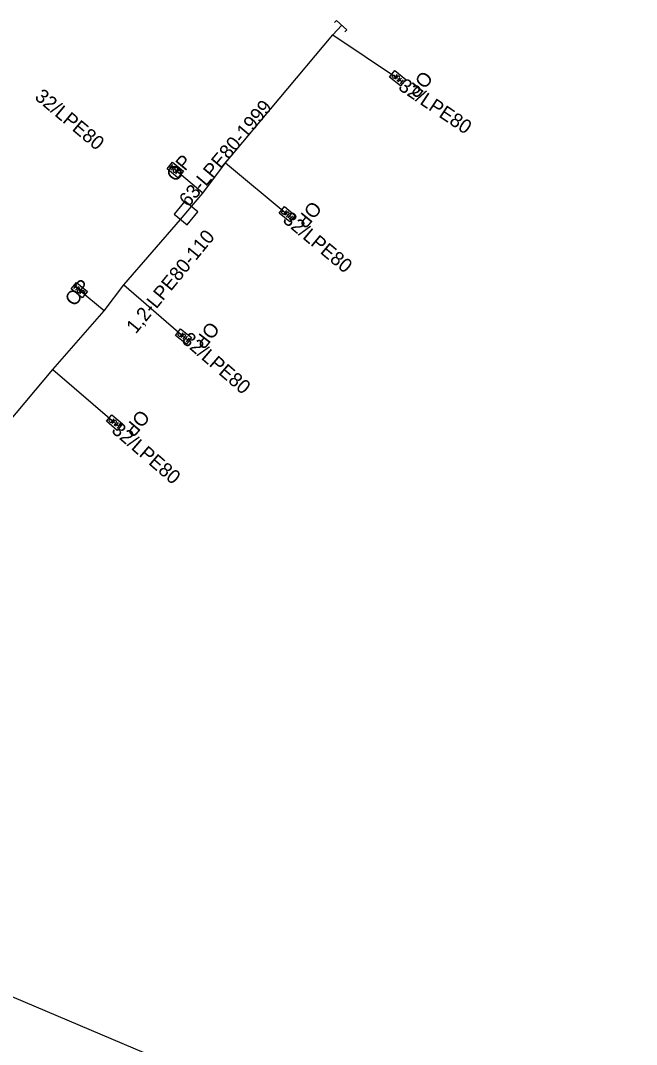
# Model space of a CAD drawing. Extents: x -762509 to -761250, y -1153000 to -1152256.
# Drawn here: x -761556.9 to -761512.9, y -1152334 to -1152260.8 of the extents above; entities that cross this region are included whole.
import ezdxf

# ---------------------------------------------------------------- set-up
doc = ezdxf.new("R2010")
doc.units = 0
for name, color, linetype in [('Vrstva 21', 7, 'Continuous'), ('Vrstva 23', 7, 'Continuous'), ('Vrstva 29', 7, 'Continuous'), ('Vrstva 31', 7, 'Continuous'), ('Vrstva 32', 7, 'Continuous')]:
    doc.layers.add(name, color=color, linetype=linetype)

msp = doc.modelspace()

# ---------------------------------------------------------------- linework, layer by layer
at = {"layer": 'Vrstva 21'}
for points in [[(-761582.89, -1152319.81), (-761576.95, -1152312.47), (-761564.9, -1152298), (-761554.61, -1152285.76), (-761550.95, -1152281.56), (-761549.55, -1152279.71), (-761545.49, -1152275.05), (-761544.72, -1152274.11), (-761543.9, -1152273.16), (-761542.29, -1152270.99), (-761534.6, -1152261.85), (-761533.98, -1152261.17)], [(-761582.89, -1152319.81), (-761579.97, -1152321.01), (-761566.93, -1152326.59), (-761564.15, -1152327.67), (-761562.41, -1152328.48), (-761561.34, -1152328.94), (-761548.12, -1152334.52), (-761539.24, -1152337.93), (-761531.97, -1152340.58), (-761528.13, -1152341.92), (-761526.3, -1152342.45), (-761512.91, -1152346.54), (-761513.62, -1152349.91), (-761513.51, -1152352.59), (-761512.99, -1152352.67)]]:
    msp.add_lwpolyline(points, dxfattribs=at)
at = {"layer": 'Vrstva 23'}
msp.add_lwpolyline([(-761533.746, -1152261.655), (-761533.611, -1152261.507), (-761534.35, -1152260.833), (-761534.485, -1152260.981)], dxfattribs=at)
at = {"layer": 'Vrstva 29'}
msp.add_lwpolyline([(-761545.03, -1152275.43), (-761544.26, -1152274.49), (-761545.18, -1152273.73), (-761545.95, -1152274.67)], close=True, dxfattribs=at)
at = {"layer": 'Vrstva 31'}
for points in [[(-761534.6, -1152261.85), (-761529.98, -1152264.96)], [(-761542.29, -1152270.99), (-761537.88, -1152274.67)], [(-761543.9, -1152273.16), (-761545.87, -1152271.51)], [(-761550.95, -1152281.56), (-761552.73, -1152280.09)], [(-761549.55, -1152279.71), (-761545.28, -1152283.4)], [(-761554.61, -1152285.76), (-761550.21, -1152289.55)]]:
    msp.add_lwpolyline(points, dxfattribs=at)
at = {"layer": 'Vrstva 32'}
for p, q in [((-761530.022, -1152264.698), (-761530.245, -1152264.967)), ((-761529.715, -1152264.952), (-761529.938, -1152265.222)), ((-761529.678, -1152265.223), (-761529.833, -1152265.095)), ((-761529.783, -1152265.35), (-761529.56, -1152265.08)), ((-761546.065, -1152271.119), (-761546.289, -1152271.387)), ((-761546.171, -1152271.246), (-761546.017, -1152271.375)), ((-761546.135, -1152271.516), (-761545.911, -1152271.248)), ((-761545.829, -1152271.773), (-761545.605, -1152271.504)), ((-761537.923, -1152274.408), (-761538.145, -1152274.678)), ((-761537.615, -1152274.661), (-761537.837, -1152274.931)), ((-761537.577, -1152274.931), (-761537.732, -1152274.804)), ((-761537.682, -1152275.059), (-761537.46, -1152274.788)), ((-761552.927, -1152279.7), (-761553.149, -1152279.97)), ((-761553.032, -1152279.828), (-761552.877, -1152279.956)), ((-761552.994, -1152280.098), (-761552.772, -1152279.828)), ((-761552.687, -1152280.352), (-761552.464, -1152280.082)), ((-761545.33, -1152283.139), (-761545.545, -1152283.415)), ((-761545.015, -1152283.384), (-761545.23, -1152283.66)), ((-761544.97, -1152283.653), (-761545.129, -1152283.53)), ((-761545.072, -1152283.783), (-761544.857, -1152283.507)), ((-761550.249, -1152289.287), (-761550.475, -1152289.554)), ((-761549.945, -1152289.545), (-761550.171, -1152289.812)), ((-761549.911, -1152289.816), (-761550.064, -1152289.686)), ((-761550.018, -1152289.942), (-761549.791, -1152289.675))]:
    msp.add_line(p, q, dxfattribs=at)
for points in [[(-761529.786, -1152265.51), (-761530.556, -1152264.872), (-761530.173, -1152264.41), (-761529.403, -1152265.048), (-761529.786, -1152265.51)], [(-761530.245, -1152264.967), (-761530.345, -1152264.884), (-761530.367, -1152264.844), (-761530.368, -1152264.822), (-761530.358, -1152264.788), (-761530.326, -1152264.749), (-761530.294, -1152264.733), (-761530.272, -1152264.73), (-761530.229, -1152264.744), (-761530.129, -1152264.827)], [(-761530.014, -1152265.158), (-761529.854, -1152264.965), (-761529.834, -1152264.919), (-761529.837, -1152264.873), (-761529.858, -1152264.833), (-761529.88, -1152264.815), (-761529.924, -1152264.801), (-761529.967, -1152264.808), (-761530.009, -1152264.837), (-761530.169, -1152265.03)], [(-761546.061, -1152270.959), (-761545.294, -1152271.601), (-761545.68, -1152272.061), (-761546.446, -1152271.419), (-761546.061, -1152270.959)], [(-761545.835, -1152271.312), (-761545.996, -1152271.504), (-761546.017, -1152271.551), (-761546.014, -1152271.596), (-761545.993, -1152271.636), (-761545.971, -1152271.654), (-761545.927, -1152271.668), (-761545.884, -1152271.662), (-761545.842, -1152271.633), (-761545.681, -1152271.441)], [(-761545.605, -1152271.504), (-761545.505, -1152271.588), (-761545.484, -1152271.628), (-761545.483, -1152271.65), (-761545.493, -1152271.684), (-761545.525, -1152271.722), (-761545.557, -1152271.739), (-761545.579, -1152271.741), (-761545.622, -1152271.727), (-761545.722, -1152271.644)], [(-761537.684, -1152275.219), (-761538.457, -1152274.585), (-761538.076, -1152274.121), (-761537.303, -1152274.755), (-761537.684, -1152275.219)], [(-761538.145, -1152274.678), (-761538.246, -1152274.596), (-761538.268, -1152274.556), (-761538.269, -1152274.534), (-761538.259, -1152274.5), (-761538.227, -1152274.461), (-761538.195, -1152274.444), (-761538.174, -1152274.442), (-761538.13, -1152274.455), (-761538.03, -1152274.537)], [(-761537.914, -1152274.868), (-761537.754, -1152274.674), (-761537.734, -1152274.628), (-761537.737, -1152274.582), (-761537.759, -1152274.543), (-761537.781, -1152274.524), (-761537.824, -1152274.511), (-761537.868, -1152274.518), (-761537.91, -1152274.547), (-761538.069, -1152274.741)], [(-761552.924, -1152279.54), (-761552.153, -1152280.177), (-761552.535, -1152280.64), (-761553.306, -1152280.003), (-761552.924, -1152279.54)], [(-761552.695, -1152279.891), (-761552.855, -1152280.085), (-761552.876, -1152280.132), (-761552.873, -1152280.177), (-761552.851, -1152280.217), (-761552.829, -1152280.235), (-761552.786, -1152280.249), (-761552.742, -1152280.242), (-761552.7, -1152280.213), (-761552.54, -1152280.019)], [(-761552.464, -1152280.082), (-761552.364, -1152280.165), (-761552.342, -1152280.205), (-761552.341, -1152280.227), (-761552.351, -1152280.261), (-761552.383, -1152280.3), (-761552.415, -1152280.316), (-761552.436, -1152280.319), (-761552.48, -1152280.306), (-761552.58, -1152280.223)], [(-761545.069, -1152283.944), (-761545.859, -1152283.33), (-761545.491, -1152282.856), (-761544.701, -1152283.47), (-761545.069, -1152283.944)], [(-761545.545, -1152283.415), (-761545.648, -1152283.336), (-761545.671, -1152283.296), (-761545.673, -1152283.274), (-761545.663, -1152283.24), (-761545.633, -1152283.2), (-761545.601, -1152283.183), (-761545.58, -1152283.179), (-761545.536, -1152283.192), (-761545.434, -1152283.272)], [(-761545.308, -1152283.599), (-761545.154, -1152283.401), (-761545.135, -1152283.354), (-761545.14, -1152283.309), (-761545.162, -1152283.27), (-761545.185, -1152283.252), (-761545.229, -1152283.24), (-761545.272, -1152283.248), (-761545.313, -1152283.278), (-761545.467, -1152283.476)], [(-761550.022, -1152290.102), (-761550.785, -1152289.455), (-761550.397, -1152288.997), (-761549.634, -1152289.644), (-761550.022, -1152290.102)], [(-761550.475, -1152289.554), (-761550.574, -1152289.47), (-761550.596, -1152289.429), (-761550.597, -1152289.408), (-761550.586, -1152289.373), (-761550.554, -1152289.335), (-761550.522, -1152289.319), (-761550.5, -1152289.317), (-761550.457, -1152289.331), (-761550.358, -1152289.415)], [(-761550.246, -1152289.748), (-761550.084, -1152289.556), (-761550.063, -1152289.51), (-761550.065, -1152289.465), (-761550.087, -1152289.424), (-761550.109, -1152289.406), (-761550.152, -1152289.391), (-761550.195, -1152289.398), (-761550.237, -1152289.426), (-761550.4, -1152289.618)]]:
    msp.add_lwpolyline(points, dxfattribs=at)

# ---------------------------------------------------------------- texts
at = {"layer": 'Vrstva 21'}
msp.add_text('63-LPE80-1999', height=1, rotation=49.9242, dxfattribs=at).set_placement((-761544.93, -1152274.21))
at = {"layer": 'Vrstva 29'}
msp.add_text('1,2-LPE80-110', height=1, rotation=50.67742, dxfattribs=at).set_placement((-761548.69, -1152283.26))
at = {"layer": 'Vrstva 31'}
for rotation, p in [(326.05313, (-761530, -1152265.72)), (326.05313, (-761530, -1152265.72)), (320.05169, (-761555.98, -1152266.39)), (320.05169, (-761555.98, -1152266.39)), (320.15611, (-761538.26, -1152275.17)), (320.15611, (-761538.26, -1152275.17)), (319.16745, (-761545.48, -1152283.75)), (319.16745, (-761545.48, -1152283.75)), (319.25959, (-761550.49, -1152290.19)), (319.25959, (-761550.49, -1152290.19))]:
    msp.add_text('32/LPE80', height=1, rotation=rotation, dxfattribs=at).set_placement(p)
at = {"layer": 'Vrstva 32'}
for rotation, p in [(230.3447, (-761528.16, -1152264.35)), (230.3447, (-761528.16, -1152264.35)), (50.05169, (-761545.84, -1152272.43)), (50.05169, (-761545.84, -1152272.43)), (230.62968, (-761536.1, -1152273.65)), (230.62968, (-761536.1, -1152273.65)), (50.44865, (-761553.08, -1152281.32)), (50.44865, (-761553.08, -1152281.32)), (232.14628, (-761543.42, -1152282.26)), (232.14628, (-761543.42, -1152282.26)), (229.70746, (-761548.37, -1152288.55)), (229.70746, (-761548.37, -1152288.55))]:
    msp.add_text('OP', height=1, rotation=rotation, dxfattribs=at).set_placement(p)

doc.saveas('drawing.dxf')
